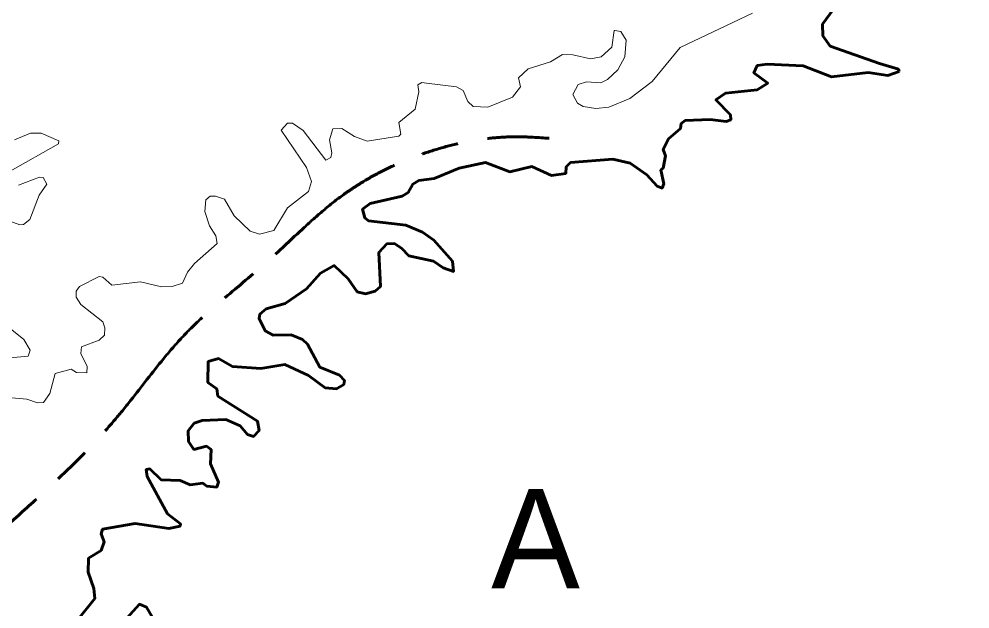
# Model space of a CAD drawing. Extents: x -1643653 to 4543381, y 1624270 to 13878484.
# Drawn here: x 584467 to 592113, y 8968607 to 8973351 of the extents above; entities that cross this region are included whole.
import ezdxf

# ---------------------------------------------------------------- set-up
doc = ezdxf.new("R2010")
doc.units = 0
doc.header["$LTSCALE"] = 200
doc.linetypes.add('LONG_DASH_SHORT_DASH', pattern=[9.9, 6, -1.2, 1.5, -1.2])
for name, color, linetype, lineweight in [('1', 7, 'Continuous', 13), ('25', 7, 'Continuous', 13), ('27', 7, 'Continuous', 53), ('28', 7, 'Continuous', 53), ('31', 7, 'Continuous', 53), ('7', 7, 'LONG_DASH_SHORT_DASH', 60)]:
    doc.layers.add(name, color=color, linetype=linetype, lineweight=lineweight)

msp = doc.modelspace()

# ---------------------------------------------------------------- linework, layer by layer
at = {"layer": '1', "lineweight": 25}
msp.add_spline([(814781, 9009175.5), (814787.2, 9009173.4), (814796.9, 9009173.4), (814799.4, 9009172.4), (814805.1, 9009174.5), (814805.6, 9009176.5), (814811.7, 9009179.5), (814811.7, 9009179.5), (814801.5, 9009181), (814790.7, 9009181.5), (814784.1, 9009183.1), (814777.4, 9009185.1), (814778.4, 9009175.5)], degree=3, dxfattribs=at)
at = {"layer": '25'}
for points in [[(591065.8, 8973500.9), (590925.8, 8973310), (590930.2, 8973216.3), (590989.7, 8973133.6), (591386.4, 8972993.6), (591539.1, 8972948.4), (591544.1, 8972929.1)], [(591065.8, 8973500.9), (590925.8, 8973310), (590930.2, 8973216.3), (590989.7, 8973133.6), (591386.4, 8972993.6), (591539.1, 8972948.4), (591544.1, 8972929.1)], [(589256.8, 8973257.4), (589304.8, 8973250.5), (589349.5, 8973181.3), (589336.7, 8973046.6), (589282, 8972943.2), (589197.1, 8972864.3), (589143.7, 8972836.4), (589028.8, 8972846.9), (588963.2, 8972823.6), (588920.5, 8972745), (588956.7, 8972674.9), (589003.3, 8972647.2), (589105, 8972632.4), (589208.9, 8972641.3), (589377.1, 8972711), (589557.5, 8972848.9), (589783.1, 8973121.1), (590364.9, 8973397.1)], [(589256.8, 8973257.4), (589304.8, 8973250.5), (589349.5, 8973181.3), (589336.7, 8973046.6), (589282, 8972943.2), (589197.1, 8972864.3), (589143.7, 8972836.4), (589028.8, 8972846.9), (588963.2, 8972823.6), (588920.5, 8972745), (588956.7, 8972674.9), (589003.3, 8972647.2), (589105, 8972632.4), (589208.9, 8972641.3), (589377.1, 8972711), (589557.5, 8972848.9), (589783.1, 8973121.1), (590364.9, 8973397.1)], [(587744.4, 8972835.9), (587983.9, 8972804.3), (588036.8, 8972776.6), (588075, 8972687.6), (588119.6, 8972647.3), (588237.5, 8972640.8), (588435.9, 8972723.7), (588499.7, 8972804.5), (588483.1, 8972879), (588561.7, 8972951.1), (588739.8, 8973006.3), (588835.7, 8973065.7), (588918.6, 8973063.5), (589063, 8973031.8), (589147.9, 8973046.8), (589234.5, 8973124.8), (589252.7, 8973258), (589256.8, 8973257.4)], [(587744.4, 8972835.9), (587983.9, 8972804.3), (588036.8, 8972776.6), (588075, 8972687.6), (588119.6, 8972647.3), (588237.5, 8972640.8), (588435.9, 8972723.7), (588499.7, 8972804.5), (588483.1, 8972879), (588561.7, 8972951.1), (588739.8, 8973006.3), (588835.7, 8973065.7), (588918.6, 8973063.5), (589063, 8973031.8), (589147.9, 8973046.8), (589234.5, 8973124.8), (589252.7, 8973258), (589256.8, 8973257.4)], [(591544.1, 8972929.1), (591451.2, 8972895.9), (591293, 8972921.2), (591000.3, 8972885.2), (590771.4, 8972974.2), (590482, 8972987.1), (590400.9, 8972976.4), (590375.5, 8972917.5), (590487.9, 8972834.1), (590400.8, 8972781.1), (590146.4, 8972755.6), (590069.9, 8972700.4), (590188.4, 8972581.5), (590190.6, 8972539), (590153.7, 8972526.2), (590022.9, 8972543.1), (589823.3, 8972534.6), (589789.5, 8972511.4), (589784.9, 8972471), (589689.6, 8972386.1), (589647, 8972301.2), (589666, 8972251.4), (589644.9, 8972152.7), (589627.8, 8972139.3), (589651.2, 8972025), (589636.7, 8971991.2), (589636.7, 8971991.2)], [(591544.1, 8972929.1), (591451.2, 8972895.9), (591293, 8972921.2), (591000.3, 8972885.2), (590771.4, 8972974.2), (590482, 8972987.1), (590400.9, 8972976.4), (590375.5, 8972917.5), (590487.9, 8972834.1), (590400.8, 8972781.1), (590146.4, 8972755.6), (590069.9, 8972700.4), (590188.4, 8972581.5), (590190.6, 8972539), (590153.7, 8972526.2), (590022.9, 8972543.1), (589823.3, 8972534.6), (589789.5, 8972511.4), (589784.9, 8972471), (589689.6, 8972386.1), (589647, 8972301.2), (589666, 8972251.4), (589644.9, 8972152.7), (589627.8, 8972139.3), (589651.2, 8972025), (589636.7, 8971991.2), (589636.7, 8971991.2)], [(585111.6, 8971279.2), (585141.3, 8971274.9), (585213.8, 8971211.3), (585443, 8971236.7), (585613.2, 8971196.4), (585698.2, 8971200.7), (585782.6, 8971228.1), (585821.2, 8971315.3), (585878.5, 8971385.4), (586058.9, 8971546.7), (586050.5, 8971606.3), (585999.6, 8971687.1), (585961.4, 8971801.8), (585969.8, 8971897.1), (586004, 8971925.1), (586046.1, 8971927.1), (586118.5, 8971901.5), (586197.3, 8971767.6), (586326.8, 8971644.7), (586399.8, 8971621.3), (586515.7, 8971651), (586626.4, 8971831.7), (586793.9, 8971963.1), (586819.5, 8972043.7), (586777.5, 8972158), (586575.5, 8972456.3), (586626.1, 8972513.3), (586666.5, 8972513.3), (586751.7, 8972453.7), (586934.4, 8972216.2), (586974.5, 8972237.3), (586982.9, 8972274.7), (586964.1, 8972379.9), (586989.7, 8972468.8), (587061.7, 8972470.9), (587164.3, 8972404.8), (587265.6, 8972369), (587521, 8972409.7), (587521, 8972409.7), (587537.4, 8972424.4), (587520.6, 8972519.8), (587652.2, 8972626), (587681.8, 8972766), (587674.8, 8972821.7), (587705.8, 8972841), (587744.4, 8972835.9)], [(585111.6, 8971279.2), (585141.3, 8971274.9), (585213.8, 8971211.3), (585443, 8971236.7), (585613.2, 8971196.4), (585698.2, 8971200.7), (585782.6, 8971228.1), (585821.2, 8971315.3), (585878.5, 8971385.4), (586058.9, 8971546.7), (586050.5, 8971606.3), (585999.6, 8971687.1), (585961.4, 8971801.8), (585969.8, 8971897.1), (586004, 8971925.1), (586046.1, 8971927.1), (586118.5, 8971901.5), (586197.3, 8971767.6), (586326.8, 8971644.7), (586399.8, 8971621.3), (586515.7, 8971651), (586626.4, 8971831.7), (586793.9, 8971963.1), (586819.5, 8972043.7), (586777.5, 8972158), (586575.5, 8972456.3), (586626.1, 8972513.3), (586666.5, 8972513.3), (586751.7, 8972453.7), (586934.4, 8972216.2), (586974.5, 8972237.3), (586982.9, 8972274.7), (586964.1, 8972379.9), (586989.7, 8972468.8), (587061.7, 8972470.9), (587164.3, 8972404.8), (587265.6, 8972369), (587521, 8972409.7), (587521, 8972409.7), (587537.4, 8972424.4), (587520.6, 8972519.8), (587652.2, 8972626), (587681.8, 8972766), (587674.8, 8972821.7), (587705.8, 8972841), (587744.4, 8972835.9)], [(584432.1, 8972379.7), (584559.6, 8972432.7), (584559.6, 8972432.7), (584644.6, 8972432.6), (584786.6, 8972370.8), (584785.8, 8972347.3), (584395, 8972126.3)], [(584432.1, 8972379.7), (584559.6, 8972432.7), (584559.6, 8972432.7), (584644.6, 8972432.6), (584786.6, 8972370.8), (584785.8, 8972347.3), (584395, 8972126.3)], [(589636.7, 8971991.2), (589598.1, 8972007.9), (589513.3, 8972099), (589381.6, 8972192.5), (589241.4, 8972224.5), (588901.3, 8972196.8), (588865.3, 8972162.9), (588863, 8972107.8), (588748.1, 8972092.9), (588748.1, 8972092.9), (588590.9, 8972165), (588412.8, 8972122.6), (588217.3, 8972196.9), (588004.9, 8972152.3), (587806, 8972067.6), (587682, 8972052.4), (587633.2, 8972022.7), (587596.9, 8971954.8), (587546.7, 8971925.3), (587289, 8971866.3), (587229.6, 8971820.7), (587248.6, 8971751), (587275.8, 8971727.9), (587576, 8971693.4), (587711.7, 8971638.2), (587803.3, 8971572.2), (587950.9, 8971402.7), (587960.4, 8971321.1)], [(589636.7, 8971991.2), (589598.1, 8972007.9), (589513.3, 8972099), (589381.6, 8972192.5), (589241.4, 8972224.5), (588901.3, 8972196.8), (588865.3, 8972162.9), (588863, 8972107.8), (588748.1, 8972092.9), (588748.1, 8972092.9), (588590.9, 8972165), (588412.8, 8972122.6), (588217.3, 8972196.9), (588004.9, 8972152.3), (587806, 8972067.6), (587682, 8972052.4), (587633.2, 8972022.7), (587596.9, 8971954.8), (587546.7, 8971925.3), (587289, 8971866.3), (587229.6, 8971820.7), (587248.6, 8971751), (587275.8, 8971727.9), (587576, 8971693.4), (587711.7, 8971638.2), (587803.3, 8971572.2), (587950.9, 8971402.7), (587960.4, 8971321.1)], [(584461.6, 8972014.2), (584630.9, 8972080), (584661.4, 8972077.8), (584690.8, 8972022.3), (584629.4, 8971933.2), (584552.9, 8971738.1), (584503.4, 8971697.7), (584472.4, 8971696.2), (584351.2, 8971742.2)], [(584461.6, 8972014.2), (584630.9, 8972080), (584661.4, 8972077.8), (584690.8, 8972022.3), (584629.4, 8971933.2), (584552.9, 8971738.1), (584503.4, 8971697.7), (584472.4, 8971696.2), (584351.2, 8971742.2)], [(587960.4, 8971321.1), (587960.4, 8971321.1), (587878.2, 8971348.9), (587800.7, 8971404.6), (587601.6, 8971447), (587546.2, 8971506.3), (587484.6, 8971544.6), (587424.8, 8971542.6), (587359.2, 8971474.4), (587373.9, 8971198.8), (587329.3, 8971162.4), (587253.1, 8971141.2), (587184.9, 8971158.2), (587112.5, 8971262.4), (587002, 8971368.3), (586889.7, 8971306.8), (586777.2, 8971181.7), (586606.9, 8971064.6), (586453.7, 8971019.6), (586403.3, 8970977.5), (586399, 8970942.1), (586445.6, 8970844.1), (586509.4, 8970807.7), (586653.8, 8970811.9), (586747.1, 8970773.8), (586785.6, 8970735.2), (586885.5, 8970550.7), (587042.4, 8970487), (587082.7, 8970444.8), (587078.6, 8970412.6), (587019.2, 8970376.5), (586928.2, 8970384.9), (586793.3, 8970485.2), (586602.9, 8970571.8), (586411.7, 8970540), (586184.3, 8970557.1), (586072, 8970620.6), (585986.8, 8970597.1), (585985.1, 8970426.9), (586057, 8970376.2), (586064.4, 8970318.2), (586383.6, 8970117.6), (586398.9, 8970043.2), (586352.2, 8969994.2), (586303.6, 8970008.9), (586245.3, 8970079.5), (586131.1, 8970130), (585940.1, 8970123.6), (585874.5, 8970100.3), (585827.6, 8970038.4), (585830, 8969952.9), (585872.2, 8969890), (585973.9, 8969915.4), (586012.3, 8969889.7), (586006, 8969772.9), (586071.7, 8969626.7), (586056.7, 8969586.3), (585978.4, 8969594.8), (585945.9, 8969618), (585842.4, 8969605.4), (585761.7, 8969641.4), (585609, 8969645.7), (585519.5, 8969734.8), (585490.3, 8969728.7), (585498.3, 8969673.3), (585661.4, 8969372.5), (585765.4, 8969291.4), (585763.8, 8969274.2), (585672.2, 8969254.8), (585400.5, 8969295.2), (585139.6, 8969248.4), (585128.7, 8969210.2), (585151.9, 8969146.5), (585128.6, 8969076.5), (585026.8, 8969016.8), (585022.1, 8968902.1), (585069.3, 8968771.8), (585077.6, 8968692.1), (584933.7, 8968514.1)], [(587960.4, 8971321.1), (587960.4, 8971321.1), (587878.2, 8971348.9), (587800.7, 8971404.6), (587601.6, 8971447), (587546.2, 8971506.3), (587484.6, 8971544.6), (587424.8, 8971542.6), (587359.2, 8971474.4), (587373.9, 8971198.8), (587329.3, 8971162.4), (587253.1, 8971141.2), (587184.9, 8971158.2), (587112.5, 8971262.4), (587002, 8971368.3), (586889.7, 8971306.8), (586777.2, 8971181.7), (586606.9, 8971064.6), (586453.7, 8971019.6), (586403.3, 8970977.5), (586399, 8970942.1), (586445.6, 8970844.1), (586509.4, 8970807.7), (586653.8, 8970811.9), (586747.1, 8970773.8), (586785.6, 8970735.2), (586885.5, 8970550.7), (587042.4, 8970487), (587082.7, 8970444.8), (587078.6, 8970412.6), (587019.2, 8970376.5), (586928.2, 8970384.9), (586793.3, 8970485.2), (586602.9, 8970571.8), (586411.7, 8970540), (586184.3, 8970557.1), (586072, 8970620.6), (585986.8, 8970597.1), (585985.1, 8970426.9), (586057, 8970376.2), (586064.4, 8970318.2), (586383.6, 8970117.6), (586398.9, 8970043.2), (586352.2, 8969994.2), (586303.6, 8970008.9), (586245.3, 8970079.5), (586131.1, 8970130), (585940.1, 8970123.6), (585874.5, 8970100.3), (585827.6, 8970038.4), (585830, 8969952.9), (585872.2, 8969890), (585973.9, 8969915.4), (586012.3, 8969889.7), (586006, 8969772.9), (586071.7, 8969626.7), (586056.7, 8969586.3), (585978.4, 8969594.8), (585945.9, 8969618), (585842.4, 8969605.4), (585761.7, 8969641.4), (585609, 8969645.7), (585519.5, 8969734.8), (585490.3, 8969728.7), (585498.3, 8969673.3), (585661.4, 8969372.5), (585765.4, 8969291.4), (585763.8, 8969274.2), (585672.2, 8969254.8), (585400.5, 8969295.2), (585139.6, 8969248.4), (585128.7, 8969210.2), (585151.9, 8969146.5), (585128.6, 8969076.5), (585026.8, 8969016.8), (585022.1, 8968902.1), (585069.3, 8968771.8), (585077.6, 8968692.1), (584933.7, 8968514.1)], [(584347.1, 8970310.6), (584528.8, 8970293.7), (584614.4, 8970263.9), (584662.6, 8970267.9), (584714.5, 8970340.6), (584757.2, 8970501.8), (584885.6, 8970535.6), (584929, 8970508.2), (585011.6, 8970506.1), (585015.9, 8970557.2), (584963, 8970661.1), (584969.3, 8970716), (585111.8, 8970769.6), (585154, 8970809.8), (585158.3, 8970866.9), (585141.3, 8970915.8), (584965.3, 8971056), (584926.9, 8971113.6), (584926.9, 8971162.3), (584954.3, 8971200.4), (585111.6, 8971279.2)], [(584347.1, 8970310.6), (584528.8, 8970293.7), (584614.4, 8970263.9), (584662.6, 8970267.9), (584714.5, 8970340.6), (584757.2, 8970501.8), (584885.6, 8970535.6), (584929, 8970508.2), (585011.6, 8970506.1), (585015.9, 8970557.2), (584963, 8970661.1), (584969.3, 8970716), (585111.8, 8970769.6), (585154, 8970809.8), (585158.3, 8970866.9), (585141.3, 8970915.8), (584965.3, 8971056), (584926.9, 8971113.6), (584926.9, 8971162.3), (584954.3, 8971200.4), (585111.6, 8971279.2)], [(584368.2, 8970884.1), (584506.1, 8970773.8), (584557, 8970686.9), (584540.2, 8970639.9), (584364.7, 8970623)], [(584368.2, 8970884.1), (584506.1, 8970773.8), (584557, 8970686.9), (584540.2, 8970639.9), (584364.7, 8970623)], [(585333.9, 8968534), (585434.5, 8968644.9), (585434.5, 8968644.9), (585492.3, 8968621), (585617.4, 8968405)], [(585333.9, 8968534), (585434.5, 8968644.9), (585434.5, 8968644.9), (585492.3, 8968621), (585617.4, 8968405)]]:
    msp.add_lwpolyline(points, dxfattribs=at)
at = {"layer": '27'}
for points in [[(591544.1, 8972929.1), (591539.1, 8972948.4), (591386.4, 8972993.6), (590989.7, 8973133.6), (590930.2, 8973216.3), (590925.8, 8973310), (591065.8, 8973500.9)], [(589636.7, 8971991.2), (589636.7, 8971991.2), (589651.2, 8972025), (589627.8, 8972139.3), (589644.9, 8972152.7), (589666, 8972251.4), (589647, 8972301.2), (589689.6, 8972386.1), (589784.9, 8972471), (589789.5, 8972511.4), (589823.3, 8972534.6), (590022.9, 8972543.1), (590153.7, 8972526.2), (590190.6, 8972539), (590188.4, 8972581.5), (590069.9, 8972700.4), (590146.4, 8972755.6), (590400.8, 8972781.1), (590487.9, 8972834.1), (590375.5, 8972917.5), (590400.9, 8972976.4), (590482, 8972987.1), (590771.4, 8972974.2), (591000.3, 8972885.2), (591293, 8972921.2), (591451.2, 8972895.9), (591544.1, 8972929.1)], [(587960.4, 8971321.1), (587950.9, 8971402.7), (587803.3, 8971572.2), (587711.7, 8971638.2), (587576, 8971693.4), (587275.8, 8971727.9), (587248.6, 8971751), (587229.6, 8971820.7), (587289, 8971866.3), (587546.7, 8971925.3), (587596.9, 8971954.8), (587633.2, 8972022.7), (587682, 8972052.4), (587806, 8972067.6), (588004.9, 8972152.3), (588217.3, 8972196.9), (588412.8, 8972122.6), (588590.9, 8972165), (588748.1, 8972092.9), (588748.1, 8972092.9), (588863, 8972107.8), (588865.3, 8972162.9), (588901.3, 8972196.8), (589241.4, 8972224.5), (589381.6, 8972192.5), (589513.3, 8972099), (589598.1, 8972007.9), (589636.7, 8971991.2)], [(584933.7, 8968514.1), (585077.6, 8968692.1), (585069.3, 8968771.8), (585022.1, 8968902.1), (585026.8, 8969016.8), (585128.6, 8969076.5), (585151.9, 8969146.5), (585128.7, 8969210.2), (585139.6, 8969248.4), (585400.5, 8969295.2), (585672.2, 8969254.8), (585763.8, 8969274.2), (585765.4, 8969291.4), (585661.4, 8969372.5), (585498.3, 8969673.3), (585490.3, 8969728.7), (585519.5, 8969734.8), (585609, 8969645.7), (585761.7, 8969641.4), (585842.4, 8969605.4), (585945.9, 8969618), (585978.4, 8969594.8), (586056.7, 8969586.3), (586071.7, 8969626.7), (586006, 8969772.9), (586012.3, 8969889.7), (585973.9, 8969915.4), (585872.2, 8969890), (585830, 8969952.9), (585827.6, 8970038.4), (585874.5, 8970100.3), (585940.1, 8970123.6), (586131.1, 8970130), (586245.3, 8970079.5), (586303.6, 8970008.9), (586352.2, 8969994.2), (586398.9, 8970043.2), (586383.6, 8970117.6), (586064.4, 8970318.2), (586057, 8970376.2), (585985.1, 8970426.9), (585986.8, 8970597.1), (586072, 8970620.6), (586184.3, 8970557.1), (586411.7, 8970540), (586602.9, 8970571.8), (586793.3, 8970485.2), (586928.2, 8970384.9), (587019.2, 8970376.5), (587078.6, 8970412.6), (587082.7, 8970444.8), (587042.4, 8970487), (586885.5, 8970550.7), (586785.6, 8970735.2), (586747.1, 8970773.8), (586653.8, 8970811.9), (586509.4, 8970807.7), (586445.6, 8970844.1), (586399, 8970942.1), (586403.3, 8970977.5), (586453.7, 8971019.6), (586606.9, 8971064.6), (586777.2, 8971181.7), (586889.7, 8971306.8), (587002, 8971368.3), (587112.5, 8971262.4), (587184.9, 8971158.2), (587253.1, 8971141.2), (587329.3, 8971162.4), (587373.9, 8971198.8), (587359.2, 8971474.4), (587424.8, 8971542.6), (587484.6, 8971544.6), (587546.2, 8971506.3), (587601.6, 8971447), (587800.7, 8971404.6), (587878.2, 8971348.9), (587960.4, 8971321.1), (587960.4, 8971321.1)], [(585617.4, 8968405), (585492.3, 8968621), (585434.5, 8968644.9), (585434.5, 8968644.9), (585333.9, 8968534)]]:
    msp.add_lwpolyline(points, dxfattribs=at)
at = {"layer": '28'}
for points in [[(591065.8, 8973500.9), (590925.8, 8973310), (590930.2, 8973216.3), (590989.7, 8973133.6), (591386.4, 8972993.6), (591539.1, 8972948.4), (591544.1, 8972929.1)], [(591065.8, 8973500.9), (590925.8, 8973310), (590930.2, 8973216.3), (590989.7, 8973133.6), (591386.4, 8972993.6), (591539.1, 8972948.4), (591544.1, 8972929.1)], [(591544.1, 8972929.1), (591451.2, 8972895.9), (591293, 8972921.2), (591000.3, 8972885.2), (590771.4, 8972974.2), (590482, 8972987.1), (590400.9, 8972976.4), (590375.5, 8972917.5), (590487.9, 8972834.1), (590400.8, 8972781.1), (590146.4, 8972755.6), (590069.9, 8972700.4), (590188.4, 8972581.5), (590190.6, 8972539), (590153.7, 8972526.2), (590022.9, 8972543.1), (589823.3, 8972534.6), (589789.5, 8972511.4), (589784.9, 8972471), (589689.6, 8972386.1), (589647, 8972301.2), (589666, 8972251.4), (589644.9, 8972152.7), (589627.8, 8972139.3), (589651.2, 8972025), (589636.7, 8971991.2), (589636.7, 8971991.2)], [(591544.1, 8972929.1), (591451.2, 8972895.9), (591293, 8972921.2), (591000.3, 8972885.2), (590771.4, 8972974.2), (590482, 8972987.1), (590400.9, 8972976.4), (590375.5, 8972917.5), (590487.9, 8972834.1), (590400.8, 8972781.1), (590146.4, 8972755.6), (590069.9, 8972700.4), (590188.4, 8972581.5), (590190.6, 8972539), (590153.7, 8972526.2), (590022.9, 8972543.1), (589823.3, 8972534.6), (589789.5, 8972511.4), (589784.9, 8972471), (589689.6, 8972386.1), (589647, 8972301.2), (589666, 8972251.4), (589644.9, 8972152.7), (589627.8, 8972139.3), (589651.2, 8972025), (589636.7, 8971991.2), (589636.7, 8971991.2)], [(589636.7, 8971991.2), (589598.1, 8972007.9), (589513.3, 8972099), (589381.6, 8972192.5), (589241.4, 8972224.5), (588901.3, 8972196.8), (588865.3, 8972162.9), (588863, 8972107.8), (588748.1, 8972092.9), (588748.1, 8972092.9), (588590.9, 8972165), (588412.8, 8972122.6), (588217.3, 8972196.9), (588004.9, 8972152.3), (587806, 8972067.6), (587682, 8972052.4), (587633.2, 8972022.7), (587596.9, 8971954.8), (587546.7, 8971925.3), (587289, 8971866.3), (587229.6, 8971820.7), (587248.6, 8971751), (587275.8, 8971727.9), (587576, 8971693.4), (587711.7, 8971638.2), (587803.3, 8971572.2), (587950.9, 8971402.7), (587960.4, 8971321.1)], [(589636.7, 8971991.2), (589598.1, 8972007.9), (589513.3, 8972099), (589381.6, 8972192.5), (589241.4, 8972224.5), (588901.3, 8972196.8), (588865.3, 8972162.9), (588863, 8972107.8), (588748.1, 8972092.9), (588748.1, 8972092.9), (588590.9, 8972165), (588412.8, 8972122.6), (588217.3, 8972196.9), (588004.9, 8972152.3), (587806, 8972067.6), (587682, 8972052.4), (587633.2, 8972022.7), (587596.9, 8971954.8), (587546.7, 8971925.3), (587289, 8971866.3), (587229.6, 8971820.7), (587248.6, 8971751), (587275.8, 8971727.9), (587576, 8971693.4), (587711.7, 8971638.2), (587803.3, 8971572.2), (587950.9, 8971402.7), (587960.4, 8971321.1)], [(587960.4, 8971321.1), (587960.4, 8971321.1), (587878.2, 8971348.9), (587800.7, 8971404.6), (587601.6, 8971447), (587546.2, 8971506.3), (587484.6, 8971544.6), (587424.8, 8971542.6), (587359.2, 8971474.4), (587373.9, 8971198.8), (587329.3, 8971162.4), (587253.1, 8971141.2), (587184.9, 8971158.2), (587112.5, 8971262.4), (587002, 8971368.3), (586889.7, 8971306.8), (586777.2, 8971181.7), (586606.9, 8971064.6), (586453.7, 8971019.6), (586403.3, 8970977.5), (586399, 8970942.1), (586445.6, 8970844.1), (586509.4, 8970807.7), (586653.8, 8970811.9), (586747.1, 8970773.8), (586785.6, 8970735.2), (586885.5, 8970550.7), (587042.4, 8970487), (587082.7, 8970444.8), (587078.6, 8970412.6), (587019.2, 8970376.5), (586928.2, 8970384.9), (586793.3, 8970485.2), (586602.9, 8970571.8), (586411.7, 8970540), (586184.3, 8970557.1), (586072, 8970620.6), (585986.8, 8970597.1), (585985.1, 8970426.9), (586057, 8970376.2), (586064.4, 8970318.2), (586383.6, 8970117.6), (586398.9, 8970043.2), (586352.2, 8969994.2), (586303.6, 8970008.9), (586245.3, 8970079.5), (586131.1, 8970130), (585940.1, 8970123.6), (585874.5, 8970100.3), (585827.6, 8970038.4), (585830, 8969952.9), (585872.2, 8969890), (585973.9, 8969915.4), (586012.3, 8969889.7), (586006, 8969772.9), (586071.7, 8969626.7), (586056.7, 8969586.3), (585978.4, 8969594.8), (585945.9, 8969618), (585842.4, 8969605.4), (585761.7, 8969641.4), (585609, 8969645.7), (585519.5, 8969734.8), (585490.3, 8969728.7), (585498.3, 8969673.3), (585661.4, 8969372.5), (585765.4, 8969291.4), (585763.8, 8969274.2), (585672.2, 8969254.8), (585400.5, 8969295.2), (585139.6, 8969248.4), (585128.7, 8969210.2), (585151.9, 8969146.5), (585128.6, 8969076.5), (585026.8, 8969016.8), (585022.1, 8968902.1), (585069.3, 8968771.8), (585077.6, 8968692.1), (584933.7, 8968514.1)], [(587960.4, 8971321.1), (587960.4, 8971321.1), (587878.2, 8971348.9), (587800.7, 8971404.6), (587601.6, 8971447), (587546.2, 8971506.3), (587484.6, 8971544.6), (587424.8, 8971542.6), (587359.2, 8971474.4), (587373.9, 8971198.8), (587329.3, 8971162.4), (587253.1, 8971141.2), (587184.9, 8971158.2), (587112.5, 8971262.4), (587002, 8971368.3), (586889.7, 8971306.8), (586777.2, 8971181.7), (586606.9, 8971064.6), (586453.7, 8971019.6), (586403.3, 8970977.5), (586399, 8970942.1), (586445.6, 8970844.1), (586509.4, 8970807.7), (586653.8, 8970811.9), (586747.1, 8970773.8), (586785.6, 8970735.2), (586885.5, 8970550.7), (587042.4, 8970487), (587082.7, 8970444.8), (587078.6, 8970412.6), (587019.2, 8970376.5), (586928.2, 8970384.9), (586793.3, 8970485.2), (586602.9, 8970571.8), (586411.7, 8970540), (586184.3, 8970557.1), (586072, 8970620.6), (585986.8, 8970597.1), (585985.1, 8970426.9), (586057, 8970376.2), (586064.4, 8970318.2), (586383.6, 8970117.6), (586398.9, 8970043.2), (586352.2, 8969994.2), (586303.6, 8970008.9), (586245.3, 8970079.5), (586131.1, 8970130), (585940.1, 8970123.6), (585874.5, 8970100.3), (585827.6, 8970038.4), (585830, 8969952.9), (585872.2, 8969890), (585973.9, 8969915.4), (586012.3, 8969889.7), (586006, 8969772.9), (586071.7, 8969626.7), (586056.7, 8969586.3), (585978.4, 8969594.8), (585945.9, 8969618), (585842.4, 8969605.4), (585761.7, 8969641.4), (585609, 8969645.7), (585519.5, 8969734.8), (585490.3, 8969728.7), (585498.3, 8969673.3), (585661.4, 8969372.5), (585765.4, 8969291.4), (585763.8, 8969274.2), (585672.2, 8969254.8), (585400.5, 8969295.2), (585139.6, 8969248.4), (585128.7, 8969210.2), (585151.9, 8969146.5), (585128.6, 8969076.5), (585026.8, 8969016.8), (585022.1, 8968902.1), (585069.3, 8968771.8), (585077.6, 8968692.1), (584933.7, 8968514.1)], [(585333.9, 8968534), (585434.5, 8968644.9), (585434.5, 8968644.9), (585492.3, 8968621), (585617.4, 8968405)], [(585333.9, 8968534), (585434.5, 8968644.9), (585434.5, 8968644.9), (585492.3, 8968621), (585617.4, 8968405)]]:
    msp.add_lwpolyline(points, dxfattribs=at)
at = {"layer": '7'}
msp.add_spline([(583719.8, 8968683.1), (584226, 8969147.1), (585263.8, 8970159.6), (585803.8, 8970817.7), (586453.4, 8971391.4), (587077.8, 8971939.8), (587744.3, 8972277.3), (588469.9, 8972403.9), (588728.8, 8972391.8)], degree=3, dxfattribs=at)

# ---------------------------------------------------------------- texts
at = {"layer": '31'}
msp.add_text('A', height=800, dxfattribs=at).set_placement((588262.9, 8968772.9))

doc.saveas('drawing.dxf')
